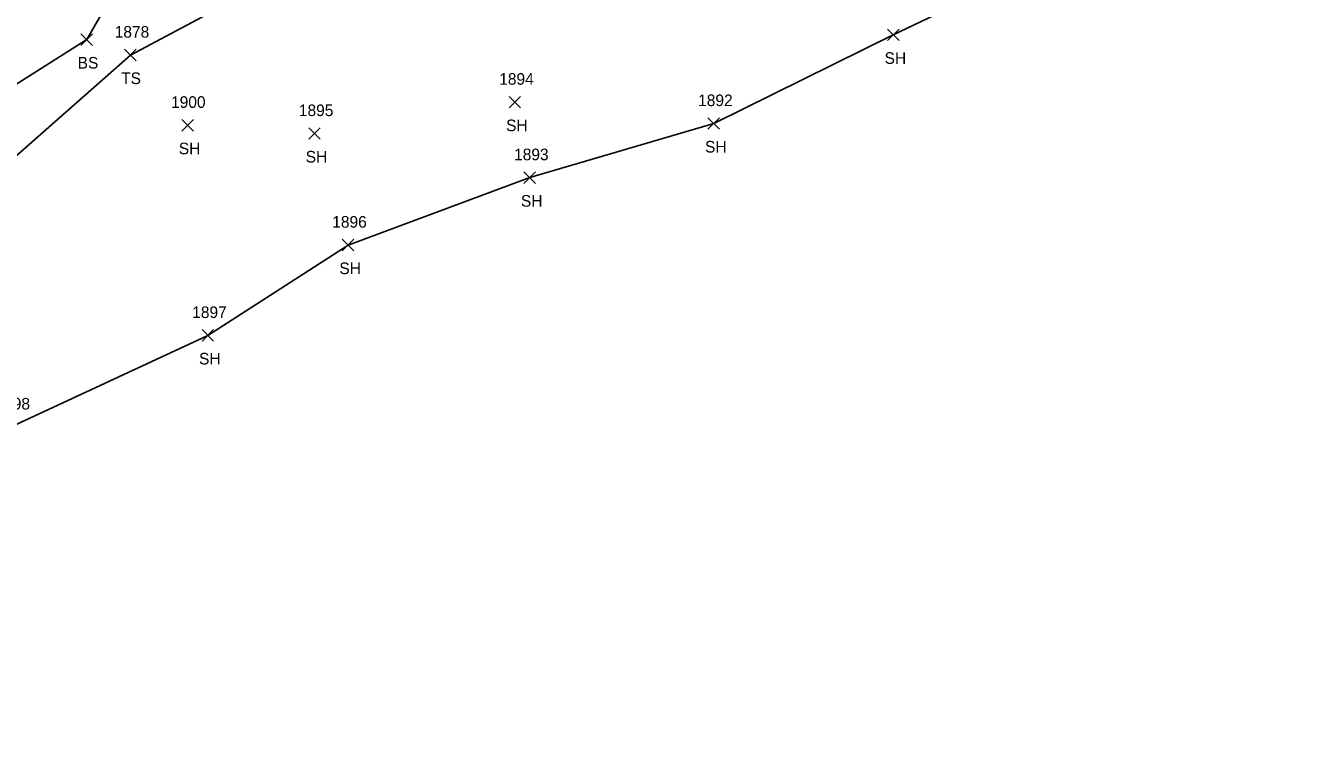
# Model space of a CAD drawing. Extents: x 1633660 to 1636532, y 388643 to 392631.
# Drawn here: x 1634396.6 to 1634615.1, y 388739.8 to 388865.4 of the extents above; entities that cross this region are included whole.
import ezdxf

# ---------------------------------------------------------------- set-up
doc = ezdxf.new("R2010")
doc.units = 0
for name, color, linetype in [('L_A', 7, 'Continuous'), ('L_I', 7, 'Continuous'), ('L_TIC', 7, 'Continuous'), ('LELB', 7, 'Continuous'), ('LSOGP', 7, 'Continuous')]:
    doc.layers.add(name, color=color, linetype=linetype)

msp = doc.modelspace()

# ---------------------------------------------------------------- linework, layer by layer
at = {"layer": 'L_TIC'}
for points in [[(1634406.22, 388861.91), (1634408.22, 388863.91)], [(1634408.22, 388861.91), (1634406.22, 388863.91)], [(1634545.28, 388862.72), (1634547.28, 388864.72)], [(1634547.28, 388862.72), (1634545.28, 388864.72)], [(1634413.75, 388859.24), (1634415.75, 388861.24)], [(1634415.75, 388859.24), (1634413.75, 388861.24)], [(1634480.03, 388851.12), (1634482.03, 388853.12)], [(1634482.03, 388851.12), (1634480.03, 388853.12)], [(1634423.62, 388847.14), (1634425.62, 388849.14)], [(1634425.62, 388847.14), (1634423.62, 388849.14)], [(1634514.33, 388847.44), (1634516.33, 388849.44)], [(1634516.33, 388847.44), (1634514.33, 388849.44)], [(1634445.49, 388845.72), (1634447.49, 388847.72)], [(1634447.49, 388845.72), (1634445.49, 388847.72)], [(1634482.59, 388838.11), (1634484.59, 388840.11)], [(1634484.59, 388838.11), (1634482.59, 388840.11)], [(1634451.29, 388826.49), (1634453.29, 388828.49)], [(1634453.29, 388826.49), (1634451.29, 388828.49)], [(1634427.1, 388810.92), (1634429.1, 388812.92)], [(1634429.1, 388810.92), (1634427.1, 388812.92)]]:
    msp.add_lwpolyline(points, dxfattribs=at)
at = {"layer": 'LELB'}
for points in [[(1634584.89, 388915.4), (1634565.24, 388902.91), (1634528.64, 388898.73), (1634496.98, 388906.62), (1634477.85, 388894.65), (1634446.93, 388893.09), (1634415.16, 388876.74), (1634407.22, 388862.91), (1634384.25, 388848.4), (1634365.18, 388835.86)], [(1634366.11, 388829.23), (1634392.92, 388840.96), (1634414.75, 388860.24), (1634439.48, 388873.42), (1634473.36, 388870.48), (1634511.37, 388872.55), (1634556.17, 388880.75), (1634584.64, 388898.02), (1634601.64, 388909.04)]]:
    msp.add_lwpolyline(points, dxfattribs=at)
at = {"layer": 'LSOGP'}
msp.add_lwpolyline([(1634218.98, 388740.85), (1634254.67, 388740.24), (1634315.25, 388739.85), (1634380.93, 388763.62), (1634394.19, 388796.15), (1634428.1, 388811.92), (1634452.29, 388827.49), (1634483.59, 388839.11), (1634515.33, 388848.44), (1634546.28, 388863.72), (1634572.45, 388876.23), (1634604.94, 388890.27), (1634644.29, 388911.66), (1634697.95, 388942.99), (1634729.71, 388982.06), (1634750.63, 388992.22), (1634777.03, 389014.48), (1634810.97, 389037.99), (1634811.65, 389038.97), (1634835.21, 389072.38), (1634837.85, 389085.95), (1634849.33, 389112.53), (1634851.42, 389137.05)], dxfattribs=at)

# ---------------------------------------------------------------- texts
at = {"layer": 'L_A'}
for s, p in [('BS', (1634405.66, 388857.91)), ('SH', (1634544.77, 388858.72)), ('TS', (1634413.16, 388855.24)), ('SH', (1634479.52, 388847.12)), ('SH', (1634423.1, 388843.14)), ('SH', (1634513.82, 388843.44)), ('SH', (1634444.98, 388841.72)), ('SH', (1634482.08, 388834.11)), ('SH', (1634450.78, 388822.49)), ('SH', (1634426.59, 388806.92))]:
    msp.add_text(s, height=2, dxfattribs=at).set_placement(p)
at = {"layer": 'L_I'}
for s, p in [('1878', (1634412.05, 388863.24)), ('1894', (1634478.34, 388855.12)), ('1900', (1634421.76, 388851.14)), ('1892', (1634512.63, 388851.44)), ('1895', (1634443.8, 388849.72)), ('1893', (1634480.9, 388842.11)), ('1896', (1634449.55, 388830.49)), ('1897', (1634425.41, 388814.92)), ('1898', (1634391.5, 388799.15))]:
    msp.add_text(s, height=2, dxfattribs=at).set_placement(p)

doc.saveas('drawing.dxf')
